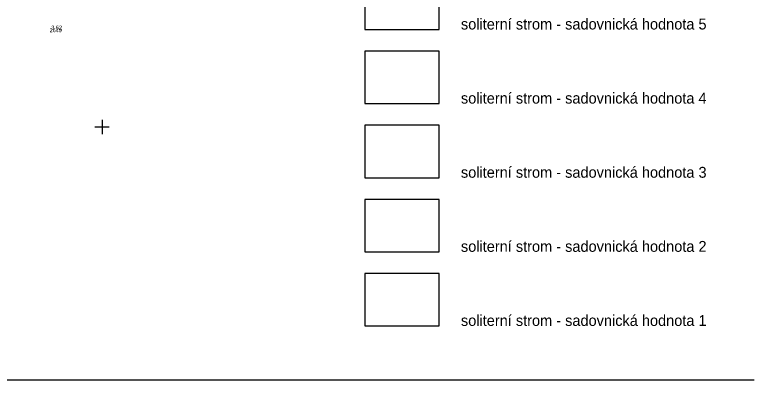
# Model space of a CAD drawing. Extents: x -740053 to -737517, y -1033516 to -1032488.
# Drawn here: x -738712 to -738610.3, y -1032685 to -1032634.5 of the extents above; entities that cross this region are included whole.
import ezdxf

# ---------------------------------------------------------------- set-up
doc = ezdxf.new("R2010")
doc.units = 0
for name, color, linetype in [('bod-cislo', 7, 'Continuous'), ('bod-oznac', 7, 'Continuous'), ('bod-vyska', 7, 'Continuous'), ('bod-vyska100', 7, 'Continuous'), ('ctv-sit', 7, 'Continuous'), ('Predmety bez rozlišeni', 7, 'Continuous')]:
    doc.layers.add(name, color=color, linetype=linetype)

# ---------------------------------------------------------------- blocks, each defined once
blk = doc.blocks.new('POINT_DISPLAY')
blk.add_line((0, 0), (0, 0))
blk = doc.blocks.new('ctvsit')
for p, q in [((2, 0), (-2, 0)), ((0, -2), (0, 2))]:
    blk.add_line(p, q)

msp = doc.modelspace()

# ---------------------------------------------------------------- linework, layer by layer
at = {"layer": 'Predmety bez rozlišeni'}
msp.add_line((-738610.01, -1032684.97), (-738715.01, -1032684.97), dxfattribs=at)
for points in [[(-738663.72, -1032636.54), (-738653.48, -1032636.54), (-738653.48, -1032629.3), (-738663.72, -1032629.3)], [(-738663.72, -1032646.77), (-738653.48, -1032646.77), (-738653.48, -1032639.54), (-738663.72, -1032639.54)], [(-738663.72, -1032657.01), (-738653.48, -1032657.01), (-738653.48, -1032649.77), (-738663.72, -1032649.77)], [(-738663.72, -1032667.24), (-738653.48, -1032667.24), (-738653.48, -1032660.01), (-738663.72, -1032660.01)], [(-738663.72, -1032677.47), (-738653.48, -1032677.47), (-738653.48, -1032670.24), (-738663.72, -1032670.24)]]:
    msp.add_lwpolyline(points, close=True, dxfattribs=at)

# ---------------------------------------------------------------- block references
at = {"layer": 'bod-oznac'}
msp.add_blockref('POINT_DISPLAY', (-738706.2, -1032636.18), dxfattribs=at)
at = {"layer": 'ctv-sit', "xscale": 0.5, "yscale": 0.5, "rotation": 180}
msp.add_blockref('ctvsit', (-738700, -1032650), dxfattribs=at)

# ---------------------------------------------------------------- texts
at = {"layer": 'bod-cislo'}
msp.add_text('2649', height=0.55, dxfattribs=at).set_placement((-738707.23, -1032636.91))
at = {"layer": 'bod-vyska'}
msp.add_text('3 62', height=0.55, dxfattribs=at).set_placement((-738707, -1032636.55))
at = {"layer": 'bod-vyska100'}
msp.add_text('283 62', height=0.05, dxfattribs=at).set_placement((-738706.37, -1032636.21))
at = {"layer": 'Predmety bez rozlišeni'}
for s, p in [('soliterní strom - sadovnická hodnota 5', (-738650.48, -1032636.54)), ('soliterní strom - sadovnická hodnota 4', (-738650.48, -1032646.77)), ('soliterní strom - sadovnická hodnota 3', (-738650.48, -1032657.01)), ('soliterní strom - sadovnická hodnota 2 ', (-738650.48, -1032667.24)), ('soliterní strom - sadovnická hodnota 1', (-738650.48, -1032677.47))]:
    msp.add_text(s, height=1.5, dxfattribs=at).set_placement(p)

doc.saveas('drawing.dxf')
